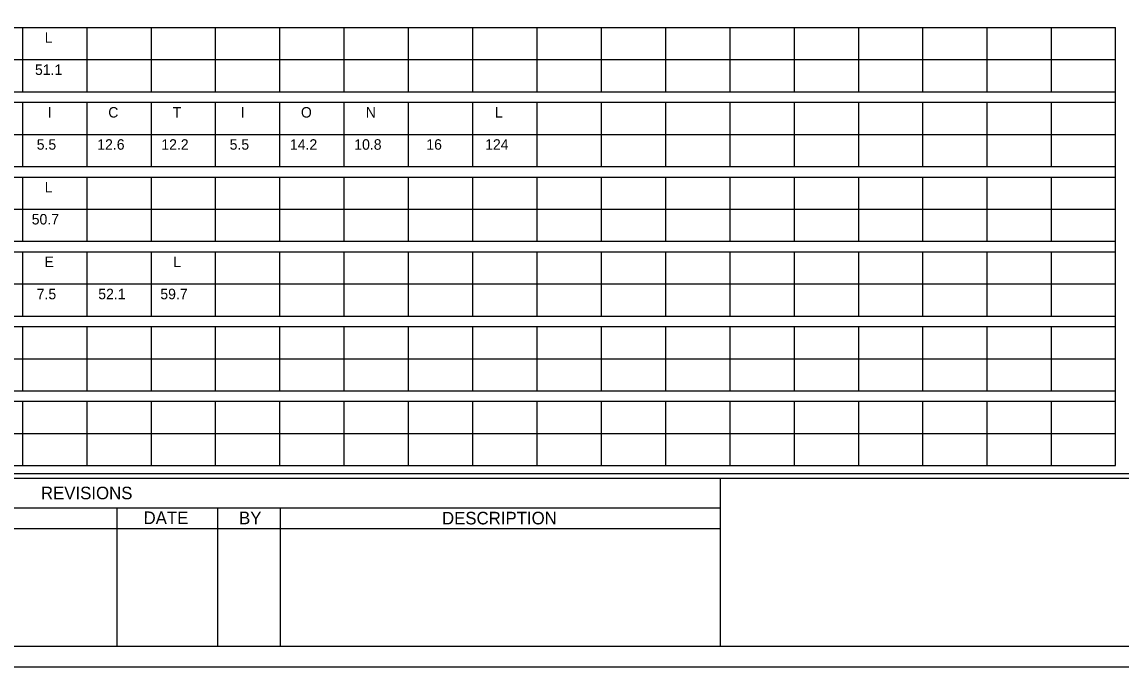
# Model space of a CAD drawing. Extents: x 122633 to 124574, y -23288 to -22025.
# Drawn here: x 122983 to 123601, y -23272 to -22910 of the extents above; entities that cross this region are included whole.
import ezdxf

# ---------------------------------------------------------------- set-up
doc = ezdxf.new("R2010")
doc.units = 0
for name, color, linetype in [('GSSign', 7, 'Continuous'), ('PlotBorder_dp', 7, 'Continuous'), ('SheetBorder_dp', 7, 'Continuous'), ('SheetLines_dp', 7, 'Continuous'), ('SheetLinesMisc2_dp', 7, 'Continuous'), ('TextMisc', 7, 'Continuous')]:
    doc.layers.add(name, color=color, linetype=linetype)

msp = doc.modelspace()

# ---------------------------------------------------------------- linework, layer by layer
at = {"layer": 'PlotBorder_dp'}
msp.add_lwpolyline([(122633.11, -23271.62), (124574.11, -23271.62), (124574.11, -22024.68), (122633.11, -22024.68)], close=True, dxfattribs=at)
at = {"layer": 'SheetBorder_dp'}
for p, q in [((122697.81, -23165.75), (124509.41, -23165.75)), ((122697.81, -23259.86), (124509.41, -23259.86))]:
    msp.add_line(p, q, dxfattribs=at)
at = {"layer": 'SheetLines_dp'}
for p, q in [((123375.4, -23165.75), (123375.4, -23259.86)), ((122697.81, -23182.22), (123375.4, -23182.22)), ((123036.6, -23182.22), (123036.6, -23259.86)), ((123093.07, -23182.22), (123093.07, -23259.86)), ((123128.36, -23182.22), (123128.36, -23259.86)), ((122697.81, -23193.98), (123375.4, -23193.98))]:
    msp.add_line(p, q, dxfattribs=at)
at = {"layer": 'SheetLinesMisc2_dp'}
for p, q in [((122709.67, -22912.77), (123597.5, -22912.77)), ((122983.52, -22912.77), (122983.52, -22948.85)), ((123019.64, -22912.77), (123019.64, -22948.85)), ((123055.75, -22912.77), (123055.75, -22948.85)), ((123091.86, -22912.77), (123091.86, -22948.85)), ((123127.99, -22912.77), (123127.99, -22948.85)), ((123164.1, -22912.77), (123164.1, -22948.85)), ((123200.22, -22912.77), (123200.22, -22948.85)), ((123236.33, -22912.77), (123236.33, -22948.85)), ((123272.46, -22912.77), (123272.46, -22948.85)), ((123308.57, -22912.77), (123308.57, -22948.85)), ((123344.68, -22912.77), (123344.68, -22948.85)), ((123380.8, -22912.77), (123380.8, -22948.85)), ((123416.92, -22912.77), (123416.92, -22948.85)), ((123453.04, -22912.77), (123453.04, -22948.85)), ((123489.15, -22912.77), (123489.15, -22948.85)), ((123525.26, -22912.77), (123525.26, -22948.85)), ((123561.39, -22912.77), (123561.39, -22948.85)), ((123597.5, -23158.6), (123597.5, -22912.77)), ((122709.67, -22930.8), (123597.5, -22930.8)), ((122709.67, -22948.85), (123597.5, -22948.85)), ((122709.67, -22954.73), (123597.5, -22954.73)), ((122983.52, -22954.73), (122983.52, -22990.8)), ((123019.64, -22954.73), (123019.64, -22990.8)), ((123055.75, -22954.73), (123055.75, -22990.8)), ((123091.86, -22954.73), (123091.86, -22990.8)), ((123127.99, -22954.73), (123127.99, -22990.8)), ((123164.1, -22954.73), (123164.1, -22990.8)), ((123200.22, -22954.73), (123200.22, -22990.8)), ((123236.33, -22954.73), (123236.33, -22990.8)), ((123272.46, -22954.73), (123272.46, -22990.8)), ((123308.57, -22954.73), (123308.57, -22990.8)), ((123344.68, -22954.73), (123344.68, -22990.8)), ((123380.8, -22954.73), (123380.8, -22990.8)), ((123416.92, -22954.73), (123416.92, -22990.8)), ((123453.04, -22954.73), (123453.04, -22990.8)), ((123489.15, -22954.73), (123489.15, -22990.8)), ((123525.26, -22954.73), (123525.26, -22990.8)), ((123561.39, -22954.73), (123561.39, -22990.8)), ((122709.67, -22972.77), (123597.5, -22972.77)), ((122709.67, -22990.8), (123597.5, -22990.8)), ((122709.67, -22996.68), (123597.5, -22996.68)), ((122983.52, -22996.68), (122983.52, -23032.75)), ((123019.64, -22996.68), (123019.64, -23032.75)), ((123055.75, -22996.68), (123055.75, -23032.75)), ((123091.86, -22996.68), (123091.86, -23032.75)), ((123127.99, -22996.68), (123127.99, -23032.75)), ((123164.1, -22996.68), (123164.1, -23032.75)), ((123200.22, -22996.68), (123200.22, -23032.75)), ((123236.33, -22996.68), (123236.33, -23032.75)), ((123272.46, -22996.68), (123272.46, -23032.75)), ((123308.57, -22996.68), (123308.57, -23032.75)), ((123344.68, -22996.68), (123344.68, -23032.75)), ((123380.8, -22996.68), (123380.8, -23032.75)), ((123416.92, -22996.68), (123416.92, -23032.75)), ((123453.04, -22996.68), (123453.04, -23032.75)), ((123489.15, -22996.68), (123489.15, -23032.75)), ((123525.26, -22996.68), (123525.26, -23032.75)), ((123561.39, -22996.68), (123561.39, -23032.75)), ((122709.67, -23014.71), (123597.5, -23014.71)), ((122709.67, -23032.75), (123597.5, -23032.75)), ((122709.67, -23038.63), (123597.5, -23038.63)), ((122983.52, -23038.63), (122983.52, -23074.71)), ((123019.64, -23038.63), (123019.64, -23074.71)), ((123055.75, -23038.63), (123055.75, -23074.71)), ((123091.86, -23038.63), (123091.86, -23074.71)), ((123127.99, -23038.63), (123127.99, -23074.71)), ((123164.1, -23038.63), (123164.1, -23074.71)), ((123200.22, -23038.63), (123200.22, -23074.71)), ((123236.33, -23038.63), (123236.33, -23074.71)), ((123272.46, -23038.63), (123272.46, -23074.71)), ((123308.57, -23038.63), (123308.57, -23074.71)), ((123344.68, -23038.63), (123344.68, -23074.71)), ((123380.8, -23038.63), (123380.8, -23074.71)), ((123416.92, -23038.63), (123416.92, -23074.71)), ((123453.04, -23038.63), (123453.04, -23074.71)), ((123489.15, -23038.63), (123489.15, -23074.71)), ((123525.26, -23038.63), (123525.26, -23074.71)), ((123561.39, -23038.63), (123561.39, -23074.71)), ((122709.67, -23056.66), (123597.5, -23056.66)), ((122709.67, -23074.71), (123597.5, -23074.71)), ((122709.67, -23080.59), (123597.5, -23080.59)), ((122983.52, -23080.59), (122983.52, -23116.66)), ((123019.64, -23080.59), (123019.64, -23116.66)), ((123055.75, -23080.59), (123055.75, -23116.66)), ((123091.86, -23080.59), (123091.86, -23116.66)), ((123127.99, -23080.59), (123127.99, -23116.66)), ((123164.1, -23080.59), (123164.1, -23116.66)), ((123200.22, -23080.59), (123200.22, -23116.66)), ((123236.33, -23080.59), (123236.33, -23116.66)), ((123272.46, -23080.59), (123272.46, -23116.66)), ((123308.57, -23080.59), (123308.57, -23116.66)), ((123344.68, -23080.59), (123344.68, -23116.66)), ((123380.8, -23080.59), (123380.8, -23116.66)), ((123416.92, -23080.59), (123416.92, -23116.66)), ((123453.04, -23080.59), (123453.04, -23116.66)), ((123489.15, -23080.59), (123489.15, -23116.66)), ((123525.26, -23080.59), (123525.26, -23116.66)), ((123561.39, -23080.59), (123561.39, -23116.66)), ((122709.67, -23098.63), (123597.5, -23098.63)), ((122709.67, -23116.66), (123597.5, -23116.66)), ((122709.67, -23122.54), (123597.5, -23122.54)), ((122983.52, -23122.54), (122983.52, -23158.6)), ((123019.64, -23122.54), (123019.64, -23158.6)), ((123055.75, -23122.54), (123055.75, -23158.6)), ((123091.86, -23122.54), (123091.86, -23158.6)), ((123127.99, -23122.54), (123127.99, -23158.6)), ((123164.1, -23122.54), (123164.1, -23158.6)), ((123200.22, -23122.54), (123200.22, -23158.6)), ((123236.33, -23122.54), (123236.33, -23158.6)), ((123272.46, -23122.54), (123272.46, -23158.6)), ((123308.57, -23122.54), (123308.57, -23158.6)), ((123344.68, -23122.54), (123344.68, -23158.6)), ((123380.8, -23122.54), (123380.8, -23158.6)), ((123416.92, -23122.54), (123416.92, -23158.6)), ((123453.04, -23122.54), (123453.04, -23158.6)), ((123489.15, -23122.54), (123489.15, -23158.6)), ((123525.26, -23122.54), (123525.26, -23158.6)), ((123561.39, -23122.54), (123561.39, -23158.6)), ((122709.67, -23140.57), (123597.5, -23140.57)), ((122709.67, -23158.6), (123597.5, -23158.6)), ((122701.01, -23162.98), (124506.26, -23162.98))]:
    msp.add_line(p, q, dxfattribs=at)

# ---------------------------------------------------------------- texts
at = {"layer": 'GSSign'}
for s, height, p in [('L', 5.88, (122996.02, -22921.37)), ('51.1', 5.882, (122990.56, -22939.4)), ('I', 5.88, (122997.7, -22963.32)), ('C', 5.88, (123031.72, -22963.32)), ('T', 5.88, (123067.99, -22963.32)), ('I', 5.88, (123106.07, -22963.32)), ('O', 5.88, (123139.95, -22963.32)), ('N', 5.88, (123176.36, -22963.32)), ('L', 5.88, (123248.89, -22963.32)), ('5.5', 5.882, (122991.54, -22981.36)), ('12.6', 5.882, (123025.56, -22981.36)), ('12.2', 5.882, (123061.54, -22981.36)), ('5.5', 5.882, (123099.91, -22981.36)), ('14.2', 5.882, (123133.79, -22981.36)), ('10.8', 5.882, (123169.92, -22981.36)), ('16', 5.882, (123210.38, -22981.36)), ('124', 5.882, (123243.43, -22981.36)), ('L', 5.88, (122996.02, -23005.28)), ('50.7', 5.882, (122988.74, -23023.31)), ('E', 5.88, (122995.88, -23047.23)), ('L', 5.88, (123068.27, -23047.23)), ('7.5', 5.882, (122991.54, -23065.27)), ('52.1', 5.882, (123026.12, -23065.27)), ('59.7', 5.882, (123060.98, -23065.27))]:
    msp.add_text(s, height=height, dxfattribs=at).set_placement(p)
at = {"layer": 'TextMisc'}
for s, p in [('REVISIONS', (122993.9, -23177.51)), ('BY', (123105.19, -23191.51))]:
    msp.add_text(s, height=7.058, dxfattribs=at).set_placement(p)
for s, height, rotation, p in [('DATE', 7.058, 359.86925, (123051.54, -23191.4)), ('DESCRIPTION', 7.0567, 0.04975, (123219.18, -23191.63))]:
    msp.add_text(s, height=height, rotation=rotation, dxfattribs=at).set_placement(p)

doc.saveas('drawing.dxf')
